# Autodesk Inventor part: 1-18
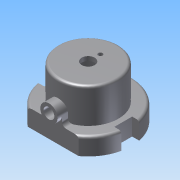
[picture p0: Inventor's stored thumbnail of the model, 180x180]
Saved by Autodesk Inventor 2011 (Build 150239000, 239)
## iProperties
Created: 2014-02
Part Number: 1-18
Document SubType Name: Modeling
Designer: Administrator
Density: 1 g/cm^3
Author: Administrator
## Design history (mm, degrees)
sketch "草图1"
  geometry: L1 (-5.876, -8.091)-(5.876, -8.091); L2 (8.154, 2.016)-(9.795, 2.016); L3 (8.154, 2.016)-(8.154, -2.106); L4 (8.154, -2.106)-(9.776, -2.106); L5 (-9.776, -2.106)-(-8.065, -2.106); L6 (-8.065, -2.106)-(-8.065, 2.02); L7 (-8.065, 2.02)-(-9.794, 2.02); A1 r 10 centre (0, 0) between (9.795, 2.016) and (-9.794, 2.02); A2 r 10 centre (0, 0) between (-9.776, -2.106) and (-5.876, -8.091); A3 r 10 centre (0, 0) between (5.876, -8.091) and (9.776, -2.106); 1 further point
  constraints: 14 end point, 6 point on circle, 3 centre point, 3 perpendicular, 2 parallel, 1 coincident, 1 collinear, 1 horizontal
extrude "拉伸1" new body sketch "草图1" distance "d1" = 4; taper "d2" = 0 deg
sketch "草图2"
  geometry: C1 r 7 at (0, 0); A1 r 10 centre (0, 0) between (9.795, 2.016) and (-9.794, 2.02) reference
  constraints: 1 centre point, 1 coincident
  dimensions: "d3" = 14 diameter of C1
extrude "拉伸2" join sketch "草图2" distance "d4" = 8; taper "d5" = 0 deg
fillet "圆角1" dims "d6" = 0.6
sketch "草图3"
  geometry: C1 r 6.4 at (0, 0) reference; C2 r 5 at (0, 0)
  constraints: 1 centre point, 1 coincident
  dimensions: "d7" = 10 diameter of C2
extrude "拉伸3" cut sketch "草图3" distance "d8" = 2; taper "d9" = 0 deg
sketch "草图4"
  geometry: C1 r 5 at (0, 0) reference; C2 r 4 at (0, 0)
  constraints: 1 centre point, 1 coincident
  dimensions: "d10" = 8 diameter of C2
extrude "拉伸4" cut sketch "草图4" distance "d11" = 9; taper "d12" = 0 deg
sketch "草图5"
  geometry: C1 r 4 at (0, 0) reference; C2 r 1.5 at (0, 0); C3 r 0.5 at (0, 2.824)
  constraints: 2 centre point, 1 coincident
  dimensions: "d13" = 3 diameter of C2; "d14" = 1 diameter of C3
extrude "拉伸5" cut sketch "草图5" stored distance "d15" = 1 (= d14); taper "d16" = 0 deg
sketch "草图6"
  geometry: L1 (11.753, 4)-(0, 4) reference; L2 (3.876, 6.147)-(3.876, 4); L3 (7.876, 6.147)-(7.876, 4); A1 r 2 centre (5.876, 6.147) between (7.876, 6.147) and (3.876, 6.147); 2 further points
  constraints: 4 end point, 2 perpendicular, 2 point on circle, 2 point on line, 2 tangent, 1 centre point, 1 midpoint, 1 vertical alignment
  dimensions: "d18" = 4 diameter of A1
extrude "拉伸6" join sketch "草图6" stored distance "d19" = 1 (= d14); taper "d20" = 0 deg
fillet "圆角2" dims "d21" = 1
sketch "草图7"
  geometry: A1 r 2 centre (5.876, 6.147) between (7.876, 6.147) and (3.876, 6.147) reference; 2 further points
  constraints: 1 coincident, 1 horizontal alignment, 2 other
extrude "拉伸7" join sketch "草图7" distance "d23" = 1; taper "d24" = 0 deg
sketch "草图8"
  geometry: C1 r 2 at (0, 0) reference; C2 r 1.25 at (0, 0); 1 further point
  constraints: 1 centre point, 1 coincident
  dimensions: "d25" = 2.5 diameter of C2
extrude "拉伸8" cut sketch "草图8" stored distance "d26" = 1; taper "d27" = 0 deg
fillet "圆角3" dims "d28" = 1
fillet "圆角4" dims "d29" = 0.6
node "实体1"
